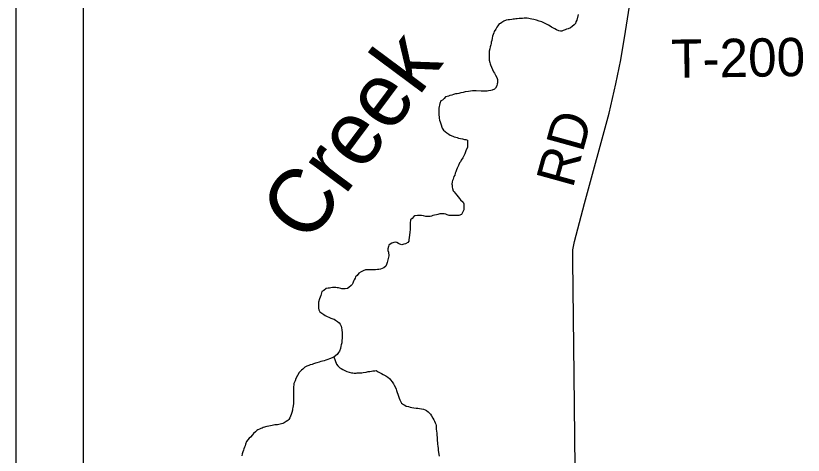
# Model space of a CAD drawing. Extents: x 0 to 34, y 0 to 22.
# Drawn here: x 2 to 3.166, y 19.221 to 19.872 of the extents above; entities that cross this region are included whole.
import ezdxf

# ---------------------------------------------------------------- set-up
doc = ezdxf.new("R2010")
doc.units = 0
for name, color, linetype in [('GM_X_Corporation', 7, 'Continuous'), ('GM_X_Minor_River', 7, 'Continuous'), ('GM_X_Minor_River_Text', 7, 'Continuous'), ('GM_X_Township_Road', 7, 'Continuous'), ('GM_X_Township_Road_Text', 7, 'Continuous'), ('SH_Data', 7, 'Continuous')]:
    doc.layers.add(name, color=color, linetype=linetype)

msp = doc.modelspace()

# ---------------------------------------------------------------- linework, layer by layer
at = {"layer": 'GM_X_Corporation'}
for points in [[(2.1, 20.3879), (2.1, 14.1)], [(2.1, 20.3879), (2.1, 15.3574)]]:
    msp.add_lwpolyline(points, dxfattribs=at)
at = {"layer": 'GM_X_Minor_River'}
for points in [[(2.7367, 19.8672), (2.7348, 19.8668), (2.7314, 19.8664), (2.7295, 19.8664), (2.7265, 19.8657), (2.7231, 19.8645), (2.72, 19.8626), (2.7181, 19.8611), (2.7162, 19.8603), (2.7143, 19.8577), (2.7128, 19.8554), (2.7109, 19.8524), (2.7086, 19.8489), (2.7082, 19.847), (2.7071, 19.8448), (2.7063, 19.8421), (2.7056, 19.8394), (2.7052, 19.8356), (2.7044, 19.8333), (2.704, 19.8314), (2.7036, 19.8292), (2.7029, 19.8265), (2.7021, 19.8235), (2.701, 19.8197), (2.701, 19.8151), (2.701, 19.8124), (2.701, 19.8101), (2.7013, 19.8067), (2.7021, 19.8033), (2.7025, 19.8014), (2.7032, 19.7995), (2.7047, 19.7961), (2.7063, 19.793), (2.7078, 19.7892), (2.7089, 19.7873), (2.7108, 19.7843), (2.7127, 19.7809), (2.7138, 19.7778), (2.7138, 19.7759), (2.7135, 19.7732), (2.7131, 19.7713), (2.7127, 19.7687), (2.7108, 19.7653), (2.7089, 19.7637), (2.7058, 19.7622), (2.7036, 19.7618), (2.7001, 19.7611), (2.6982, 19.7607), (2.6956, 19.7607), (2.6929, 19.7607), (2.6895, 19.7607), (2.6819, 19.7611), (2.6796, 19.7611), (2.6766, 19.7611), (2.6735, 19.7607), (2.6705, 19.7604), (2.6659, 19.7596), (2.6625, 19.7588), (2.6591, 19.7581), (2.6561, 19.7573), (2.6538, 19.7569), (2.6515, 19.7566), (2.6485, 19.7558), (2.6458, 19.7547), (2.6431, 19.7543), (2.6412, 19.7535), (2.639, 19.7528), (2.6367, 19.7524), (2.6348, 19.7497), (2.6321, 19.7475), (2.6298, 19.7463), (2.6283, 19.7425), (2.6268, 19.7357), (2.6268, 19.7296), (2.6268, 19.7269), (2.6268, 19.725), (2.6271, 19.7227), (2.6271, 19.7205), (2.6279, 19.7178), (2.6287, 19.7151), (2.6294, 19.7121), (2.6317, 19.706), (2.6336, 19.703), (2.6362, 19.7011), (2.6385, 19.6991), (2.6416, 19.6969), (2.6435, 19.6957), (2.6473, 19.6938), (2.6492, 19.6931), (2.6518, 19.6923), (2.6537, 19.6919), (2.656, 19.6911), (2.6587, 19.6908), (2.6617, 19.69), (2.6647, 19.6892), (2.6666, 19.6889), (2.6689, 19.6881), (2.6689, 19.6812), (2.6689, 19.679), (2.6689, 19.6771), (2.6674, 19.6736)], [(2.8329, 19.8743), (2.831, 19.866), (2.8298, 19.8633), (2.8291, 19.861), (2.8272, 19.8591), (2.8241, 19.8564), (2.8215, 19.8545), (2.8184, 19.853), (2.8158, 19.8523), (2.8139, 19.8515), (2.8108, 19.8504), (2.8089, 19.8496), (2.807, 19.8496), (2.8044, 19.85), (2.8009, 19.8515), (2.7983, 19.853), (2.7956, 19.8546), (2.7937, 19.8557), (2.7918, 19.8569), (2.7892, 19.8584), (2.7869, 19.8595), (2.7842, 19.861), (2.7823, 19.8618), (2.7793, 19.8633), (2.7774, 19.8641), (2.7755, 19.8645), (2.7713, 19.866), (2.7694, 19.8664), (2.7675, 19.8668), (2.7645, 19.8675), (2.7618, 19.8679), (2.7599, 19.8683), (2.7573, 19.8687), (2.755, 19.8687), (2.7531, 19.8687), (2.7508, 19.8683), (2.7481, 19.8683), (2.7459, 19.8683), (2.7428, 19.8679), (2.7409, 19.8679), (2.7386, 19.8675), (2.7367, 19.8672)], [(2.6674, 19.6736), (2.6651, 19.6679), (2.6632, 19.6641), (2.662, 19.6619), (2.6598, 19.6584), (2.6586, 19.6562), (2.6575, 19.6543), (2.656, 19.6505), (2.6548, 19.6486), (2.654, 19.6466), (2.6529, 19.644), (2.6521, 19.6413), (2.651, 19.639), (2.6502, 19.6364), (2.6491, 19.6341), (2.648, 19.6303), (2.6468, 19.6284), (2.6464, 19.6265), (2.646, 19.6231), (2.6464, 19.6212), (2.6464, 19.6185), (2.6468, 19.6166), (2.6479, 19.6132), (2.6494, 19.6113), (2.651, 19.6094), (2.6532, 19.6067), (2.6555, 19.6041), (2.6574, 19.6018), (2.6589, 19.5999), (2.6627, 19.5961), (2.6635, 19.5938), (2.6639, 19.5915), (2.6639, 19.5896), (2.6639, 19.585), (2.6616, 19.5808), (2.6601, 19.5782), (2.6563, 19.5767), (2.6525, 19.5763), (2.6498, 19.5763), (2.6475, 19.5763), (2.6456, 19.5763), (2.6437, 19.5763), (2.6418, 19.5767), (2.6392, 19.5774), (2.6369, 19.5786), (2.6346, 19.579), (2.6312, 19.579), (2.6281, 19.579), (2.6251, 19.5782), (2.6232, 19.5775), (2.6202, 19.5771), (2.6179, 19.5763), (2.6156, 19.5756), (2.6137, 19.5752), (2.6118, 19.5748), (2.6091, 19.5752), (2.6072, 19.5752), (2.6042, 19.576), (2.6012, 19.5763), (2.5985, 19.5767), (2.5951, 19.5767), (2.5913, 19.576), (2.5894, 19.5752), (2.5871, 19.5722), (2.5848, 19.5699), (2.5844, 19.5653), (2.5844, 19.5623), (2.584, 19.5558), (2.5836, 19.5516), (2.5833, 19.5474), (2.5821, 19.5406), (2.5821, 19.5387), (2.5806, 19.5364), (2.5775, 19.5345), (2.5749, 19.5338), (2.5718, 19.533), (2.5688, 19.5338), (2.5669, 19.5349), (2.5643, 19.5364), (2.562, 19.5368), (2.5601, 19.5364), (2.557, 19.5353), (2.5544, 19.5342), (2.5528, 19.5323), (2.5521, 19.5304), (2.5509, 19.5269), (2.5513, 19.5247), (2.5521, 19.522), (2.5525, 19.5167), (2.5513, 19.511), (2.5502, 19.5068), (2.5494, 19.5037), (2.5483, 19.5015), (2.5452, 19.4988), (2.5429, 19.498), (2.5403, 19.4969), (2.538, 19.4965), (2.5357, 19.4965), (2.5331, 19.4958), (2.5308, 19.4958), (2.5281, 19.4958)], [(2.5281, 19.4958), (2.5258, 19.4961), (2.5239, 19.4961), (2.522, 19.4961), (2.5201, 19.4962), (2.5179, 19.4958), (2.5148, 19.4946), (2.5118, 19.4931), (2.5083, 19.4912), (2.5057, 19.4878), (2.5034, 19.4855), (2.5026, 19.4836), (2.5011, 19.4813), (2.5004, 19.4791), (2.4992, 19.4764), (2.4981, 19.4745), (2.4969, 19.4726), (2.4935, 19.4696), (2.4916, 19.4684), (2.4878, 19.4677), (2.4855, 19.4677), (2.4832, 19.468), (2.4813, 19.4684), (2.4783, 19.4692), (2.476, 19.4692), (2.4741, 19.4696), (2.4722, 19.4696), (2.4692, 19.4696), (2.4665, 19.4692), (2.4646, 19.4688), (2.4627, 19.4688), (2.4597, 19.4681), (2.4563, 19.4654), (2.4536, 19.4639), (2.4517, 19.4578), (2.4498, 19.4529), (2.4486, 19.4479), (2.4483, 19.4426), (2.4486, 19.4392), (2.449, 19.4365), (2.4505, 19.4338), (2.4562, 19.4296), (2.4581, 19.4285), (2.4612, 19.427), (2.4638, 19.4258), (2.4669, 19.4243), (2.4695, 19.4236), (2.4714, 19.4228), (2.4737, 19.4216), (2.4767, 19.4194), (2.479, 19.4175), (2.4805, 19.4156), (2.482, 19.4125), (2.4824, 19.4102), (2.4832, 19.4072), (2.4836, 19.4026), (2.4835, 19.3988), (2.4835, 19.3969), (2.4835, 19.3943), (2.4832, 19.392), (2.4828, 19.3901), (2.4828, 19.3878), (2.482, 19.3851), (2.4816, 19.3828), (2.4812, 19.3794), (2.4793, 19.3756), (2.4782, 19.3733), (2.4759, 19.3707), (2.4717, 19.3673), (2.4695, 19.3661), (2.4664, 19.3646), (2.4645, 19.3642), (2.4622, 19.3631), (2.4592, 19.3623), (2.4569, 19.3612), (2.4546, 19.3608), (2.452, 19.3601), (2.4493, 19.3593), (2.4459, 19.3582), (2.444, 19.3578), (2.4409, 19.3566), (2.439, 19.3559), (2.436, 19.3551), (2.4341, 19.3544), (2.4311, 19.3532), (2.428, 19.3517), (2.4254, 19.349), (2.4235, 19.3475), (2.4212, 19.3456), (2.4197, 19.3437), (2.4151, 19.335), (2.4139, 19.3316), (2.412, 19.3278), (2.4117, 19.3259), (2.4113, 19.3224), (2.4113, 19.3205), (2.4113, 19.3186), (2.4116, 19.3167), (2.4116, 19.3141), (2.4116, 19.3118), (2.4116, 19.3091)], [(2.4712, 19.367), (2.4751, 19.3562), (2.477, 19.3536), (2.4801, 19.3509), (2.482, 19.3498), (2.4843, 19.3482), (2.4865, 19.3471), (2.4884, 19.3463), (2.4903, 19.3456), (2.4938, 19.3444), (2.4972, 19.3433), (2.4994, 19.3433), (2.5013, 19.3429), (2.504, 19.3429), (2.5059, 19.3433), (2.5086, 19.3433), (2.5108, 19.3436), (2.5127, 19.3436), (2.5146, 19.344), (2.5188, 19.3444), (2.5219, 19.3452), (2.5245, 19.3455), (2.5268, 19.3459), (2.5287, 19.3463), (2.5321, 19.3463), (2.534, 19.3467), (2.5367, 19.3448), (2.5386, 19.344), (2.5416, 19.3425), (2.5443, 19.341), (2.5462, 19.3398), (2.5481, 19.3391), (2.5511, 19.3372), (2.5534, 19.3352), (2.5553, 19.333), (2.5576, 19.3299), (2.5595, 19.3269), (2.5606, 19.325), (2.5625, 19.3215), (2.5633, 19.3193), (2.564, 19.3174), (2.5652, 19.3143), (2.5659, 19.312), (2.5667, 19.3086), (2.5678, 19.306), (2.5689, 19.3033), (2.5716, 19.2987), (2.5743, 19.2964), (2.5765, 19.2953), (2.5784, 19.2942), (2.5815, 19.2934), (2.5841, 19.2926), (2.5868, 19.2919), (2.5898, 19.2915), (2.5929, 19.2911), (2.5955, 19.2911), (2.5982, 19.2907), (2.6008, 19.2903), (2.6039, 19.2896), (2.6062, 19.2888), (2.6084, 19.2877), (2.6111, 19.2854), (2.6141, 19.282), (2.6157, 19.2797), (2.6179, 19.2762), (2.6194, 19.274), (2.6202, 19.2717), (2.6213, 19.2694), (2.6221, 19.2675), (2.6225, 19.2652), (2.6229, 19.2629), (2.6229, 19.2599), (2.6232, 19.2572), (2.6236, 19.2542), (2.6236, 19.2504), (2.624, 19.2481), (2.624, 19.2454), (2.6244, 19.2428), (2.6247, 19.2401), (2.6247, 19.2378), (2.6251, 19.2348), (2.6255, 19.2314), (2.6259, 19.2283), (2.627, 19.2199)], [(2.4116, 19.3091), (2.4116, 19.3068), (2.4112, 19.3038), (2.4112, 19.3015), (2.4112, 19.2981), (2.4109, 19.2947), (2.4105, 19.292), (2.4101, 19.2901), (2.4097, 19.2882), (2.4089, 19.2844), (2.4078, 19.2817), (2.4059, 19.2768), (2.4044, 19.2745), (2.4029, 19.2726), (2.4006, 19.2711), (2.3975, 19.2692), (2.3956, 19.2684), (2.3937, 19.2677), (2.3915, 19.2673), (2.3896, 19.2669), (2.3877, 19.2665), (2.3839, 19.2662), (2.382, 19.2658), (2.3797, 19.2654), (2.3774, 19.2647), (2.3751, 19.2643), (2.3721, 19.2639), (2.3667, 19.2624), (2.3648, 19.2616), (2.3629, 19.2609), (2.361, 19.2601), (2.3588, 19.259), (2.3569, 19.2582), (2.355, 19.2559), (2.3523, 19.2536), (2.3508, 19.2517), (2.3477, 19.2483), (2.3458, 19.2464), (2.3439, 19.2441), (2.342, 19.2415), (2.3405, 19.2377), (2.3397, 19.2354), (2.3386, 19.2331), (2.3378, 19.2308), (2.3371, 19.2286), (2.3363, 19.2263), (2.3352, 19.2236), (2.3348, 19.2206)]]:
    msp.add_lwpolyline(points, dxfattribs=at)
at = {"layer": 'GM_X_Township_Road'}
msp.add_lwpolyline([(2.8299, 18.8735), (2.8303, 19.065), (2.8273, 19.3405), (2.8254, 19.51), (2.8254, 19.5256), (2.8278, 19.5381), (2.8424, 19.5943), (2.879, 19.7279), (2.889, 19.7716), (2.8964, 19.8073), (2.903, 19.8491), (2.9089, 19.8864)], dxfattribs=at)
at = {"layer": 'SH_Data'}
for p, q in [((2, 21), (2, 14)), ((2.1, 20.9), (2.1, 14.1))]:
    msp.add_line(p, q, dxfattribs=at)

# ---------------------------------------------------------------- texts
at = {"layer": 'GM_X_Minor_River_Text'}
msp.add_text('Creek', height=0.09475, rotation=53.3364, dxfattribs=at).set_placement((2.4326, 19.5316))
at = {"layer": 'GM_X_Township_Road_Text'}
for s, rotation, p in [('T-200', 0.8431, (2.9712, 19.7802)), ('RD', 74.5294, (2.8249, 19.6156))]:
    msp.add_text(s, height=0.05682, rotation=rotation, dxfattribs=at).set_placement(p)

doc.saveas('drawing.dxf')
